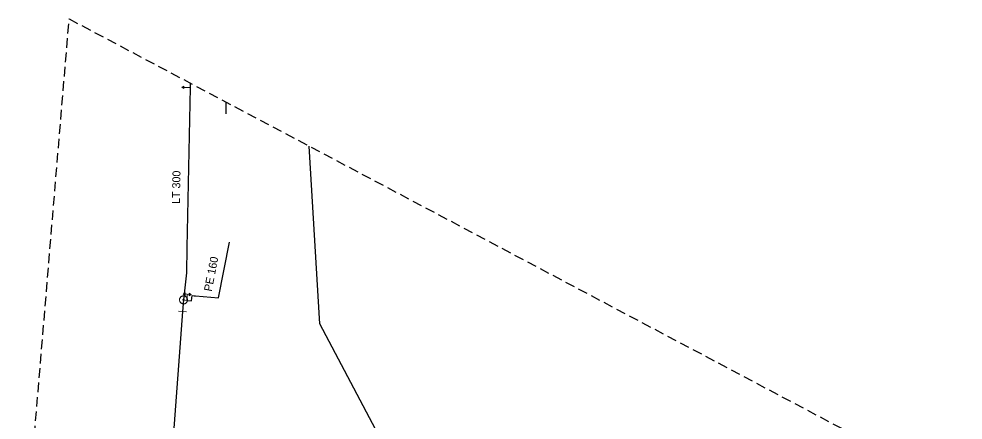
# Model space of a CAD drawing. Extents: x -692311 to -690519, y -971696 to -970899.
# Drawn here: x -692311.1 to -692193.2, y -970948.8 to -970898.7 of the extents above; entities that cross this region are included whole.
import ezdxf

# ---------------------------------------------------------------- set-up
doc = ezdxf.new("R2010")
doc.units = 0
doc.header["$LTSCALE"] = 0.4
doc.linetypes.add('MEDIUM_DASHED', pattern=[4.5, 3, -1.5])
for name, color, linetype, lineweight in [('1', 7, 'MEDIUM_DASHED', 25), ('14', 7, 'Continuous', 13), ('17', 7, 'Continuous', 25), ('34', 7, 'Continuous', 13), ('47', 7, 'Continuous', 13)]:
    doc.layers.add(name, color=color, linetype=linetype, lineweight=lineweight)

msp = doc.modelspace()

# ---------------------------------------------------------------- linework, layer by layer
at = {"layer": '1'}
msp.add_lwpolyline([(-691377.453, -971285.953), (-691463.283, -971177.096), (-691580.514, -971177.096), (-691632.849, -971177.096), (-691781.481, -971235.711), (-691971.982, -971202.217), (-692089.213, -971128.947), (-692311.114, -970974.035), (-692304.834, -970898.672), (-692166.669, -970971.942), (-691976.169, -971133.134), (-691904.993, -971149.882), (-691798.229, -971170.816), (-691674.718, -971116.387), (-691582.607, -971118.48), (-691415.135, -971114.294)], dxfattribs=at)
at = {"layer": '14'}
msp.add_line((-692290.543, -970933.791), (-692290.145, -970933.885), dxfattribs=at)
at = {"layer": '17'}
for p, q in [((-692289.696, -970906.7), (-692289.704, -970907.241)), ((-692285.267, -970909.049), (-692285.268, -970910.546)), ((-692290.543, -970933.791), (-692290.69, -970935.236)), ((-692290.69, -970935.236), (-692293.079, -970967.41))]:
    msp.add_line(p, q, dxfattribs=at)
for points in [[(-692289.704, -970907.241), (-692290.12, -970927.249), (-692290.181, -970930.425), (-692290.543, -970933.791)], [(-692264.611, -970953.671), (-692273.526, -970936.77), (-692274.836, -970914.581)], [(-692290.145, -970933.885), (-692289.568, -970933.921), (-692289.471, -970933.232), (-692289.234, -970933.276), (-692289.068, -970933.289), (-692286.164, -970933.524), (-692284.818, -970926.561)]]:
    msp.add_lwpolyline(points, dxfattribs=at)
at = {"layer": '34'}
for p, q in [((-692290.744, -970907.233), (-692290.744, -970907.223)), ((-692290.714, -970907.253), (-692290.714, -970907.202)), ((-692290.684, -970907.274), (-692290.684, -970907.183)), ((-692290.654, -970907.294), (-692290.654, -970907.163)), ((-692290.624, -970907.313), (-692290.624, -970907.143)), ((-692290.594, -970907.334), (-692290.593, -970907.123)), ((-692290.564, -970907.354), (-692290.564, -970907.103)), ((-692290.534, -970907.375), (-692290.534, -970907.084)), ((-692289.704, -970907.24), (-692290.504, -970907.229)), ((-692290.354, -970933.237), (-692290.588, -970933.054)), ((-692290.564, -970933.039), (-692290.566, -970933.071)), ((-692290.534, -970933.026), (-692290.539, -970933.089)), ((-692290.509, -970933.009), (-692290.517, -970933.111)), ((-692290.485, -970932.994), (-692290.495, -970933.128)), ((-692290.456, -970932.981), (-692290.469, -970933.147)), ((-692290.432, -970932.967), (-692290.447, -970933.163)), ((-692290.406, -970932.953), (-692290.424, -970933.181)), ((-692290.381, -970932.935), (-692290.401, -970933.202)), ((-692290.353, -970932.922), (-692290.375, -970933.22)), ((-692290.093, -970933.086), (-692290.144, -970933.884)), ((-692289.814, -970932.956), (-692289.831, -970933.255)), ((-692289.788, -970932.973), (-692289.803, -970933.241)), ((-692289.766, -970932.994), (-692289.777, -970933.222)), ((-692289.742, -970933.011), (-692289.752, -970933.208)), ((-692289.72, -970933.028), (-692289.728, -970933.194)), ((-692289.693, -970933.045), (-692289.7, -970933.179)), ((-692289.671, -970933.063), (-692289.676, -970933.164)), ((-692289.648, -970933.083), (-692289.651, -970933.146)), ((-692289.62, -970933.1), (-692289.622, -970933.132)), ((-692290.192, -970935.286), (-692291.187, -970935.184))]:
    msp.add_line(p, q, dxfattribs=at)
msp.add_lwpolyline([(-692290.504, -970907.063), (-692290.752, -970907.228), (-692290.504, -970907.394)], close=True, dxfattribs=at)
for points in [[(-692290.588, -970933.054), (-692290.328, -970932.907), (-692290.354, -970933.237)], [(-692289.855, -970933.269), (-692289.598, -970933.117), (-692290.588, -970933.054)], [(-692289.598, -970933.117), (-692289.837, -970932.939), (-692289.855, -970933.269)]]:
    msp.add_lwpolyline(points, dxfattribs=at)
at = {"layer": '47'}
for points in [[(-692290.056, -970933.904), (-692290.047, -970933.853), (-692290.043, -970933.8), (-692290.045, -970933.749), (-692290.051, -970933.697), (-692290.064, -970933.646), (-692290.082, -970933.596), (-692290.105, -970933.55), (-692290.133, -970933.505), (-692290.164, -970933.464), (-692290.201, -970933.426), (-692290.241, -970933.392), (-692290.284, -970933.363), (-692290.33, -970933.338), (-692290.379, -970933.318), (-692290.429, -970933.304), (-692290.48, -970933.295), (-692290.533, -970933.291), (-692290.585, -970933.293), (-692290.636, -970933.299), (-692290.687, -970933.312), (-692290.737, -970933.33), (-692290.784, -970933.353), (-692290.829, -970933.381), (-692290.87, -970933.412), (-692290.907, -970933.449), (-692290.941, -970933.489), (-692290.971, -970933.532), (-692290.995, -970933.578), (-692291.015, -970933.627), (-692291.029, -970933.677), (-692291.038, -970933.728), (-692291.042, -970933.781), (-692291.041, -970933.833), (-692291.034, -970933.884), (-692291.021, -970933.935), (-692291.004, -970933.985), (-692290.981, -970934.032), (-692290.953, -970934.077), (-692290.921, -970934.118), (-692290.884, -970934.155), (-692290.844, -970934.189), (-692290.802, -970934.219), (-692290.755, -970934.243), (-692290.706, -970934.263), (-692290.656, -970934.277), (-692290.605, -970934.286), (-692290.552, -970934.29), (-692290.501, -970934.289), (-692290.449, -970934.282), (-692290.398, -970934.269), (-692290.348, -970934.252), (-692290.302, -970934.229), (-692290.257, -970934.201), (-692290.216, -970934.169), (-692290.178, -970934.132), (-692290.144, -970934.092), (-692290.115, -970934.05), (-692290.09, -970934.003), (-692290.07, -970933.954)], [(-692290.463, -970933.809), (-692290.461, -970933.8), (-692290.461, -970933.792), (-692290.461, -970933.784), (-692290.462, -970933.775), (-692290.464, -970933.767), (-692290.467, -970933.759), (-692290.471, -970933.751), (-692290.475, -970933.744), (-692290.481, -970933.737), (-692290.486, -970933.731), (-692290.493, -970933.725), (-692290.5, -970933.72), (-692290.508, -970933.716), (-692290.515, -970933.713), (-692290.524, -970933.711), (-692290.533, -970933.709), (-692290.541, -970933.709), (-692290.549, -970933.709), (-692290.558, -970933.71), (-692290.566, -970933.712), (-692290.574, -970933.715), (-692290.582, -970933.719), (-692290.589, -970933.723), (-692290.597, -970933.729), (-692290.602, -970933.734), (-692290.608, -970933.741), (-692290.613, -970933.748), (-692290.617, -970933.756), (-692290.62, -970933.763), (-692290.622, -970933.772), (-692290.624, -970933.781), (-692290.624, -970933.789), (-692290.624, -970933.797), (-692290.623, -970933.806), (-692290.621, -970933.814), (-692290.619, -970933.822), (-692290.614, -970933.83), (-692290.61, -970933.837), (-692290.604, -970933.845), (-692290.599, -970933.85), (-692290.592, -970933.856), (-692290.585, -970933.861), (-692290.577, -970933.865), (-692290.57, -970933.868), (-692290.561, -970933.87), (-692290.552, -970933.872), (-692290.544, -970933.872), (-692290.536, -970933.872), (-692290.527, -970933.871), (-692290.519, -970933.869), (-692290.511, -970933.867), (-692290.503, -970933.862), (-692290.496, -970933.858), (-692290.489, -970933.852), (-692290.483, -970933.847), (-692290.477, -970933.84), (-692290.472, -970933.833), (-692290.468, -970933.825), (-692290.465, -970933.818)]]:
    msp.add_lwpolyline(points, close=True, dxfattribs=at)

# ---------------------------------------------------------------- texts
at = {"layer": '1'}
for s, rotation, p in [('LT 300', 89, (-692290.993, -970921.811)), ('PE 160', 79, (-692287.027, -970932.8))]:
    msp.add_text(s, height=1, rotation=rotation, dxfattribs=at).set_placement(p)

doc.saveas('drawing.dxf')
